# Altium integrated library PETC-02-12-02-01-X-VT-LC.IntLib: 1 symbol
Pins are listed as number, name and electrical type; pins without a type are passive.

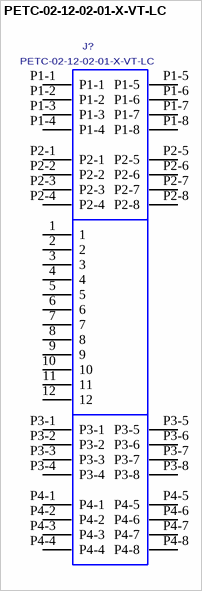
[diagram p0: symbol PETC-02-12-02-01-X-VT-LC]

## PETC-02-12-02-01-X-VT-LC
designator J?
VERTICAL POWER TERMINAL, 2 POWER PINS PER END,12 SIGNAL PINS.; MANUFACTURER: SAMTEC
footprint PETC-02-12-02-01-X-VT-LC
pins: 1, 2, 3, 4, 5, 6, 7, 8, 9, 10, 11, 12, P1-1, P1-2, P1-3, P1-4, P1-5, P1-6, P1-7, P1-8, P2-1, P2-2, P2-3, P2-4, P2-5, P2-6, P2-7, P2-8, P3-1, P3-2, P3-3, P3-4, P3-5, P3-6, P3-7, P3-8, P4-1, P4-2, P4-3, P4-4, P4-5, P4-6, P4-7, P4-8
